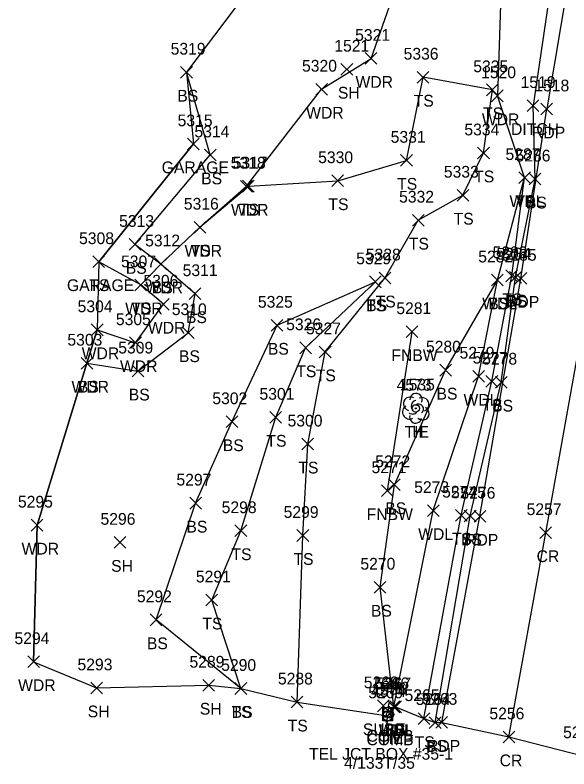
# Model space of a CAD drawing. Extents: x 1509053 to 1511576, y 400838 to 402572.
# Drawn here: x 1509634.8 to 1509729.1, y 401157.7 to 401286.1 of the extents above; entities that cross this region are included whole.
import ezdxf

# ---------------------------------------------------------------- set-up
doc = ezdxf.new("R2010")
doc.units = 0
for name, color, linetype in [('C_A', 7, 'Continuous'), ('C_I', 7, 'Continuous'), ('CBP', 7, 'Continuous'), ('D_A', 7, 'Continuous'), ('D_I', 7, 'Continuous'), ('D_TIC', 7, 'Continuous'), ('DD', 7, 'Continuous'), ('L_A', 7, 'Continuous'), ('L_I', 7, 'Continuous'), ('L_TIC', 7, 'Continuous'), ('LAWA', 7, 'Continuous'), ('LBC', 7, 'Continuous'), ('LELB', 7, 'Continuous'), ('LFNC', 7, 'Continuous'), ('LSOGP', 7, 'Continuous'), ('LTD', 7, 'Continuous'), ('P_A', 7, 'Continuous'), ('P_I', 7, 'Continuous'), ('P_TIC', 7, 'Continuous'), ('PET', 7, 'Continuous'), ('PRC', 7, 'Continuous'), ('U_A', 7, 'Continuous'), ('U_C', 7, 'Continuous'), ('U_I', 7, 'Continuous'), ('U_TIC', 7, 'Continuous'), ('UDEFAULT', 7, 'Continuous'), ('UP', 7, 'Continuous')]:
    doc.layers.add(name, color=color, linetype=linetype)

msp = doc.modelspace()

# ---------------------------------------------------------------- linework, layer by layer
at = {"layer": 'CBP'}
for centre, radius in [((1509703.04, 401219.14), 0.625), ((1509703.04, 401219.14), 0.0833), ((1509698.7, 401167), 0.625), ((1509698.7, 401167), 0.0833)]:
    msp.add_circle(centre, radius, dxfattribs=at)
at = {"layer": 'D_TIC'}
for points in [[(1509722.02, 401269.7), (1509724.02, 401271.7)], [(1509724.02, 401269.7), (1509722.02, 401271.7)]]:
    msp.add_lwpolyline(points, dxfattribs=at)
at = {"layer": 'DD'}
msp.add_lwpolyline([(1509730.43, 401320.85), (1509723.02, 401270.7)], dxfattribs=at)
at = {"layer": 'L_TIC'}
for points in [[(1509694.42, 401277.73), (1509696.42, 401279.73)], [(1509696.42, 401277.73), (1509694.42, 401279.73)], [(1509663, 401275.38), (1509665, 401277.38)], [(1509665, 401275.38), (1509663, 401277.38)], [(1509690.3, 401275.88), (1509692.3, 401277.88)], [(1509692.3, 401275.88), (1509690.3, 401277.88)], [(1509703.28, 401274.53), (1509705.28, 401276.53)], [(1509705.28, 401274.53), (1509703.28, 401276.53)], [(1509703.28, 401274.53), (1509705.28, 401276.53)], [(1509705.28, 401274.53), (1509703.28, 401276.53)], [(1509686.01, 401272.48), (1509688.01, 401274.48)], [(1509688.01, 401272.48), (1509686.01, 401274.48)], [(1509715.09, 401272.38), (1509717.09, 401274.38)], [(1509717.09, 401272.38), (1509715.09, 401274.38)], [(1509715.94, 401271.36), (1509717.94, 401273.36)], [(1509717.94, 401271.36), (1509715.94, 401273.36)], [(1509664.18, 401263.18), (1509666.18, 401265.18)], [(1509666.18, 401263.18), (1509664.18, 401265.18)], [(1509667.06, 401261.29), (1509669.06, 401263.29)], [(1509669.06, 401261.29), (1509667.06, 401263.29)], [(1509713.58, 401261.63), (1509715.58, 401263.63)], [(1509715.58, 401261.63), (1509713.58, 401263.63)], [(1509700.47, 401260.37), (1509702.47, 401262.37)], [(1509702.47, 401260.37), (1509700.47, 401262.37)], [(1509720.58, 401257.43), (1509722.58, 401259.43)], [(1509722.58, 401257.43), (1509720.58, 401259.43)], [(1509720.58, 401257.43), (1509722.58, 401259.43)], [(1509722.58, 401257.43), (1509720.58, 401259.43)], [(1509722.35, 401257.18), (1509724.35, 401259.18)], [(1509724.35, 401257.18), (1509722.35, 401259.18)], [(1509673.22, 401255.95), (1509675.22, 401257.95)], [(1509675.22, 401255.95), (1509673.22, 401257.95)], [(1509673.55, 401255.98), (1509675.55, 401257.98)], [(1509675.55, 401255.98), (1509673.55, 401257.98)], [(1509688.76, 401256.9), (1509690.76, 401258.9)], [(1509690.76, 401256.9), (1509688.76, 401258.9)], [(1509710.08, 401254.43), (1509712.08, 401256.43)], [(1509712.08, 401254.43), (1509710.08, 401256.43)], [(1509702.46, 401250.18), (1509704.46, 401252.18)], [(1509704.46, 401250.18), (1509702.46, 401252.18)], [(1509665.3, 401248.98), (1509667.3, 401250.98)], [(1509667.3, 401248.98), (1509665.3, 401250.98)], [(1509665.3, 401248.98), (1509667.3, 401250.98)], [(1509667.3, 401248.98), (1509665.3, 401250.98)], [(1509654.23, 401246.05), (1509656.23, 401248.05)], [(1509656.23, 401246.05), (1509654.23, 401248.05)], [(1509648.05, 401243.11), (1509650.05, 401245.11)], [(1509650.05, 401243.11), (1509648.05, 401245.11)], [(1509648.05, 401243.11), (1509650.05, 401245.11)], [(1509650.05, 401243.11), (1509648.05, 401245.11)], [(1509658.66, 401242.72), (1509660.66, 401244.72)], [(1509660.66, 401242.72), (1509658.66, 401244.72)], [(1509658.66, 401242.72), (1509660.66, 401244.72)], [(1509660.66, 401242.72), (1509658.66, 401244.72)], [(1509696.8, 401240.33), (1509698.8, 401242.33)], [(1509698.8, 401240.33), (1509696.8, 401242.33)], [(1509718.38, 401240.71), (1509720.38, 401242.71)], [(1509720.38, 401240.71), (1509718.38, 401242.71)], [(1509719.02, 401240.47), (1509721.02, 401242.47)], [(1509721.02, 401240.47), (1509719.02, 401242.47)], [(1509655.2, 401239.16), (1509657.2, 401241.16)], [(1509657.2, 401239.16), (1509655.2, 401241.16)], [(1509655.2, 401239.16), (1509657.2, 401241.16)], [(1509657.2, 401239.16), (1509655.2, 401241.16)], [(1509695.16, 401239.68), (1509697.16, 401241.68)], [(1509697.16, 401239.68), (1509695.16, 401241.68)], [(1509695.16, 401239.68), (1509697.16, 401241.68)], [(1509697.16, 401239.68), (1509695.16, 401241.68)], [(1509715.94, 401239.99), (1509717.94, 401241.99)], [(1509717.94, 401239.99), (1509715.94, 401241.99)], [(1509715.94, 401239.99), (1509717.94, 401241.99)], [(1509717.94, 401239.99), (1509715.94, 401241.99)], [(1509664.47, 401237.66), (1509666.47, 401239.66)], [(1509666.47, 401237.66), (1509664.47, 401239.66)], [(1509659.07, 401235.87), (1509661.07, 401237.87)], [(1509661.07, 401235.87), (1509659.07, 401237.87)], [(1509647.79, 401231.51), (1509649.79, 401233.51)], [(1509649.79, 401231.51), (1509647.79, 401233.51)], [(1509678.42, 401232.28), (1509680.42, 401234.28)], [(1509680.42, 401232.28), (1509678.42, 401234.28)], [(1509663.28, 401231.02), (1509665.28, 401233.02)], [(1509665.28, 401231.02), (1509663.28, 401233.02)], [(1509701.42, 401231.19), (1509703.42, 401233.19)], [(1509703.42, 401231.19), (1509701.42, 401233.19)], [(1509654.32, 401229.31), (1509656.32, 401231.31)], [(1509656.32, 401229.31), (1509654.32, 401231.31)], [(1509683.29, 401228.45), (1509685.29, 401230.45)], [(1509685.29, 401228.45), (1509683.29, 401230.45)], [(1509686.61, 401227.75), (1509688.61, 401229.75)], [(1509688.61, 401227.75), (1509686.61, 401229.75)], [(1509646.06, 401225.82), (1509648.06, 401227.82)], [(1509648.06, 401225.82), (1509646.06, 401227.82)], [(1509646.06, 401225.82), (1509648.06, 401227.82)], [(1509648.06, 401225.82), (1509646.06, 401227.82)], [(1509654.73, 401224.48), (1509656.73, 401226.48)], [(1509656.73, 401224.48), (1509654.73, 401226.48)], [(1509707.13, 401224.64), (1509709.13, 401226.64)], [(1509709.13, 401224.64), (1509707.13, 401226.64)], [(1509712.75, 401223.61), (1509714.75, 401225.61)], [(1509714.75, 401223.61), (1509712.75, 401225.61)], [(1509714.99, 401222.76), (1509716.99, 401224.76)], [(1509716.99, 401222.76), (1509714.99, 401224.76)], [(1509716.61, 401222.59), (1509718.61, 401224.59)], [(1509718.61, 401222.59), (1509716.61, 401224.59)], [(1509678.2, 401216.61), (1509680.2, 401218.61)], [(1509680.2, 401216.61), (1509678.2, 401218.61)], [(1509670.74, 401215.85), (1509672.74, 401217.85)], [(1509672.74, 401215.85), (1509670.74, 401217.85)], [(1509683.64, 401212.05), (1509685.64, 401214.05)], [(1509685.64, 401212.05), (1509683.64, 401214.05)], [(1509698.4, 401205.12), (1509700.4, 401207.12)], [(1509700.4, 401205.12), (1509698.4, 401207.12)], [(1509697.21, 401204.1), (1509699.21, 401206.1)], [(1509699.21, 401204.1), (1509697.21, 401206.1)], [(1509664.55, 401201.99), (1509666.55, 401203.99)], [(1509666.55, 401201.99), (1509664.55, 401203.99)], [(1509705.03, 401200.72), (1509707.03, 401202.72)], [(1509707.03, 401200.72), (1509705.03, 401202.72)], [(1509709.79, 401199.94), (1509711.79, 401201.94)], [(1509711.79, 401199.94), (1509709.79, 401201.94)], [(1509711.3, 401199.82), (1509713.3, 401201.82)], [(1509713.3, 401199.82), (1509711.3, 401201.82)], [(1509637.56, 401198.24), (1509639.56, 401200.24)], [(1509639.56, 401198.24), (1509637.56, 401200.24)], [(1509672.25, 401197.29), (1509674.25, 401199.29)], [(1509674.25, 401197.29), (1509672.25, 401199.29)], [(1509682.81, 401196.48), (1509684.81, 401198.48)], [(1509684.81, 401196.48), (1509682.81, 401198.48)], [(1509651.68, 401195.31), (1509653.68, 401197.31)], [(1509653.68, 401195.31), (1509651.68, 401197.31)], [(1509695.96, 401187.67), (1509697.96, 401189.67)], [(1509697.96, 401187.67), (1509695.96, 401189.67)], [(1509667.29, 401185.49), (1509669.29, 401187.49)], [(1509669.29, 401185.49), (1509667.29, 401187.49)], [(1509657.82, 401182.12), (1509659.82, 401184.12)], [(1509659.82, 401182.12), (1509657.82, 401184.12)], [(1509636.97, 401174.99), (1509638.97, 401176.99)], [(1509638.97, 401174.99), (1509636.97, 401176.99)], [(1509666.78, 401170.98), (1509668.78, 401172.98)], [(1509668.78, 401170.98), (1509666.78, 401172.98)], [(1509647.7, 401170.52), (1509649.7, 401172.52)], [(1509649.7, 401170.52), (1509647.7, 401172.52)], [(1509672.26, 401170.43), (1509674.26, 401172.43)], [(1509674.26, 401170.43), (1509672.26, 401172.43)], [(1509672.26, 401170.43), (1509674.26, 401172.43)], [(1509674.26, 401170.43), (1509672.26, 401172.43)], [(1509681.83, 401168.11), (1509683.83, 401170.11)], [(1509683.83, 401168.11), (1509681.83, 401170.11)], [(1509698.31, 401167.31), (1509700.31, 401169.31)], [(1509700.31, 401167.31), (1509698.31, 401169.31)], [(1509698.31, 401167.31), (1509700.31, 401169.31)], [(1509700.31, 401167.31), (1509698.31, 401169.31)], [(1509703.44, 401165.29), (1509705.44, 401167.29)], [(1509705.44, 401165.29), (1509703.44, 401167.29)], [(1509705.35, 401164.63), (1509707.35, 401166.63)], [(1509707.35, 401164.63), (1509705.35, 401166.63)]]:
    msp.add_lwpolyline(points, dxfattribs=at)
at = {"layer": 'LAWA'}
for points in [[(1509718.6, 401322.35), (1509716.94, 401272.36)], [(1509637.97, 401175.99), (1509638.56, 401199.24), (1509647.06, 401226.82), (1509648.79, 401232.51), (1509655.32, 401230.31), (1509660.07, 401236.87), (1509656.2, 401240.16), (1509659.66, 401243.72), (1509666.3, 401249.98), (1509674.22, 401256.95), (1509687.01, 401273.48), (1509695.42, 401278.73), (1509701.27, 401295.44), (1509681.69, 401309.59)], [(1509721.58, 401258.43), (1509716.94, 401272.36)], [(1509699.31, 401168.31), (1509706.03, 401201.72), (1509713.75, 401224.61), (1509716.94, 401240.99), (1509721.58, 401258.43)]]:
    msp.add_lwpolyline(points, dxfattribs=at)
at = {"layer": 'LBC'}
msp.add_lwpolyline([(1509649.05, 401244.11), (1509665.18, 401264.18)], dxfattribs=at)
at = {"layer": 'LELB'}
for points in [[(1509647.06, 401226.82), (1509655.73, 401225.48), (1509664.28, 401232.02), (1509665.47, 401238.66), (1509659.66, 401243.72), (1509655.23, 401247.05), (1509668.06, 401262.29), (1509664, 401276.38)], [(1509666.3, 401249.98), (1509674.55, 401256.98), (1509689.76, 401257.9), (1509701.47, 401261.37), (1509704.28, 401275.53)], [(1509682.83, 401169.11), (1509683.81, 401197.48), (1509684.64, 401213.05), (1509687.61, 401228.75), (1509697.8, 401241.33), (1509703.46, 401251.18), (1509711.08, 401255.43), (1509714.58, 401262.63), (1509716.09, 401273.38), (1509704.28, 401275.53)], [(1509723.35, 401258.18), (1509723.02, 401270.7)], [(1509704.44, 401166.29), (1509710.79, 401200.94), (1509715.99, 401223.76), (1509719.38, 401241.71), (1509721.58, 401258.43)], [(1509706.35, 401165.63), (1509712.3, 401200.82), (1509717.61, 401223.59), (1509720.02, 401241.47), (1509723.35, 401258.18)], [(1509656.2, 401240.16), (1509649.05, 401244.11)], [(1509673.26, 401171.43), (1509658.82, 401183.12), (1509665.55, 401202.99), (1509671.74, 401216.85), (1509679.42, 401233.28), (1509696.16, 401240.68)], [(1509673.26, 401171.43), (1509668.29, 401186.49), (1509673.25, 401198.29), (1509679.2, 401217.61), (1509684.29, 401229.45), (1509696.16, 401240.68)], [(1509699.31, 401168.31), (1509696.96, 401188.67), (1509699.4, 401206.12), (1509708.13, 401225.64), (1509716.94, 401240.99)]]:
    msp.add_lwpolyline(points, dxfattribs=at)
at = {"layer": 'LFNC'}
msp.add_lwpolyline([(1509698.21, 401205.1), (1509702.42, 401232.19)], dxfattribs=at)
at = {"layer": 'LSOGP'}
msp.add_lwpolyline([(1509676.9, 401293.5), (1509664, 401276.38), (1509665.18, 401264.18), (1509649.05, 401244.11), (1509648.79, 401232.51), (1509647.06, 401226.82), (1509638.56, 401199.24), (1509637.97, 401175.99), (1509648.7, 401171.52), (1509667.78, 401171.98), (1509673.26, 401171.43), (1509682.83, 401169.11), (1509698.26, 401166.76), (1509699.6, 401168.3), (1509704.44, 401166.29), (1509706.35, 401165.63), (1509707.47, 401165.66), (1509718.9, 401163.18), (1509731.47, 401159.97)], dxfattribs=at)
at = {"layer": 'LTD'}
msp.add_line((1509703.03, 401219.2), (1509703.03, 401219.2), dxfattribs=at)
msp.add_line((1509703.03, 401219.2), (1509703.03, 401219.2), dxfattribs=at)
msp.add_arc((1509703.08, 401220.63), 1.05, 335.5272, 180.9563, dxfattribs=at)
for centre, major_axis, ratio, start_param, end_param in [((1509702.24, 401219.87), (1.21, -0.51), 0.895232, 1.570796, 4.712389), ((1509702.82, 401219.66), (-0.208, -0.792), 0.645439, 3.141593, 6.283185), ((1509704.07, 401219.78), (-1.14, -0.48), 0.949671, 1.570796, 4.712389), ((1509701.95, 401218.49), (0.58, -1.04), 0.959034, 3.141593, 6.283185), ((1509703.53, 401219.03), (-0.5, 0.667), 0.989748, 3.141593, 6.283185), ((1509704.03, 401218.37), (-1.09, 0.79), 0.841452, 1.570796, 4.712389), ((1509703.03, 401217.7), (0.26, 1.06), 0.942809, 1.570796, 4.712389), ((1509702.57, 401218.45), (-0.625, -0.083), 0.423636, 0, 3.141593)]:
    msp.add_ellipse(centre, major_axis=major_axis, ratio=ratio, start_param=start_param, end_param=end_param, dxfattribs=at)
at = {"layer": 'P_TIC'}
for points in [[(1509724.35, 401269.12), (1509726.35, 401271.12)], [(1509726.35, 401269.12), (1509724.35, 401271.12)], [(1509719.93, 401240.28), (1509721.93, 401242.28)], [(1509721.93, 401240.28), (1509719.93, 401242.28)], [(1509712.96, 401199.75), (1509714.96, 401201.75)], [(1509714.96, 401199.75), (1509712.96, 401201.75)], [(1509724.18, 401196.96), (1509726.18, 401198.96)], [(1509726.18, 401196.96), (1509724.18, 401198.96)], [(1509706.47, 401164.66), (1509708.47, 401166.66)], [(1509708.47, 401164.66), (1509706.47, 401166.66)], [(1509717.9, 401162.18), (1509719.9, 401164.18)], [(1509719.9, 401162.18), (1509717.9, 401164.18)]]:
    msp.add_lwpolyline(points, dxfattribs=at)
at = {"layer": 'PET'}
for points in [[(1509741.68, 401369.7), (1509733.72, 401319.89), (1509725.35, 401270.12)], [(1509720.93, 401241.28), (1509725.35, 401270.12)], [(1509707.47, 401165.66), (1509713.96, 401200.75), (1509720.93, 401241.28)]]:
    msp.add_lwpolyline(points, dxfattribs=at)
at = {"layer": 'PRC'}
msp.add_lwpolyline([(1509718.9, 401163.18), (1509725.18, 401197.96), (1509732.62, 401239.49)], dxfattribs=at)
at = {"layer": 'U_TIC'}
for points in [[(1509696.5, 401167.47), (1509698.5, 401169.47)], [(1509698.5, 401167.47), (1509696.5, 401169.47)]]:
    msp.add_lwpolyline(points, dxfattribs=at)
at = {"layer": 'UDEFAULT'}
for points in [[(1509698.6, 401167.3), (1509700.6, 401169.3)], [(1509700.6, 401167.3), (1509698.6, 401169.3)]]:
    msp.add_lwpolyline(points, dxfattribs=at)
at = {"layer": 'UP'}
for p, q in [((1509697.44, 401166.53), (1509697.44, 401168.2)), ((1509697.44, 401168.2), (1509699.11, 401168.2)), ((1509698.51, 401168.43), (1509698.26, 401167.59)), ((1509698.52, 401169.03), (1509698.27, 401168.2)), ((1509699.11, 401168.2), (1509699.11, 401166.53)), ((1509697.43, 401165.93), (1509697.43, 401167.59)), ((1509697.43, 401167.59), (1509699.09, 401167.59)), ((1509698.26, 401166.76), (1509698.26, 401166.76)), ((1509698.27, 401167.37), (1509698.27, 401167.37)), ((1509699.09, 401167.59), (1509699.09, 401165.93)), ((1509699.09, 401165.93), (1509697.43, 401165.93)), ((1509699.11, 401166.53), (1509697.44, 401166.53)), ((1509698.01, 401165.09), (1509698.26, 401165.93)), ((1509698.02, 401165.7), (1509698.27, 401166.53))]:
    msp.add_line(p, q, dxfattribs=at)
for centre in [(1509698.27, 401167.37), (1509698.26, 401166.76)]:
    msp.add_circle(centre, 0.833, dxfattribs=at)

# ---------------------------------------------------------------- texts
at = {"layer": 'C_A'}
for p in [(1509701.12, 401214.14), (1509696.78, 401162)]:
    msp.add_text('TIE', height=2, dxfattribs=at).set_placement(p)
at = {"layer": 'C_I'}
for s, p in [('4573', (1509699.78, 401222.14)), ('4574', (1509695.44, 401170))]:
    msp.add_text(s, height=2, dxfattribs=at).set_placement(p)
at = {"layer": 'D_A'}
msp.add_text('DITCH', height=2, dxfattribs=at).set_placement((1509719.26, 401265.7))
at = {"layer": 'D_I'}
msp.add_text('1519', height=2, dxfattribs=at).set_placement((1509720.89, 401273.7))
at = {"layer": 'L_A'}
for s, p in [('WDR', (1509692.78, 401273.73)), ('BS', (1509662.44, 401271.38)), ('SH', (1509689.78, 401271.89)), ('TS', (1509702.69, 401270.53)), ('TS', (1509702.69, 401270.53)), ('WDR', (1509684.38, 401268.48)), ('WDR', (1509714.3, 401267.36)), ('TS', (1509714.5, 401268.38)), ('GARAGE', (1509659.78, 401259.18)), ('BS', (1509666.5, 401257.29)), ('TS', (1509712.99, 401257.63)), ('TS', (1509699.87, 401256.37)), ('WDL', (1509719, 401253.43)), ('TS', (1509719.99, 401253.43)), ('BS', (1509721.79, 401253.18)), ('WDR', (1509671.58, 401251.95)), ('TS', (1509672.96, 401251.98)), ('TS', (1509688.17, 401252.9)), ('TS', (1509709.49, 401250.43)), ('TS', (1509701.87, 401246.18)), ('WDR', (1509663.67, 401244.98)), ('TS', (1509664.71, 401244.98)), ('BS', (1509653.67, 401242.05)), ('GARAGE', (1509643.65, 401239.11)), ('TS', (1509647.46, 401239.11)), ('WDR', (1509657.02, 401238.72)), ('BS', (1509658.1, 401238.72)), ('TS', (1509717.79, 401236.71)), ('BS', (1509718.46, 401236.47)), ('WDR', (1509653.56, 401235.16)), ('TS', (1509654.61, 401235.16)), ('TS', (1509694.57, 401235.68)), ('BS', (1509694.6, 401235.68)), ('TS', (1509696.21, 401236.33)), ('WDL', (1509714.36, 401235.99)), ('BS', (1509715.38, 401235.99)), ('BS', (1509663.91, 401233.66)), ('WDR', (1509657.43, 401231.87)), ('WDR', (1509646.16, 401227.51)), ('BS', (1509677.86, 401228.28)), ('BS', (1509662.72, 401227.02)), ('FNBW', (1509698.89, 401227.19)), ('WDR', (1509652.68, 401225.31)), ('TS', (1509682.7, 401224.45)), ('TS', (1509686.02, 401223.75)), ('WDR', (1509644.42, 401221.82)), ('BS', (1509645.5, 401221.82)), ('BS', (1509654.17, 401220.48)), ('BS', (1509706.57, 401220.64)), ('WDL', (1509711.17, 401219.61)), ('TS', (1509714.4, 401218.76)), ('BS', (1509716.05, 401218.59)), ('H', (1509702.46, 401214.2)), ('TS', (1509677.61, 401212.61)), ('BS', (1509670.18, 401211.85)), ('TS', (1509683.05, 401208.05)), ('BS', (1509697.84, 401201.12)), ('FNBW', (1509694.68, 401200.1)), ('BS', (1509663.99, 401197.99)), ('WDL', (1509703.45, 401196.72)), ('TS', (1509709.2, 401195.94)), ('BS', (1509710.74, 401195.82)), ('WDR', (1509635.92, 401194.24)), ('TS', (1509671.66, 401193.29)), ('TS', (1509682.22, 401192.48)), ('SH', (1509651.17, 401191.31)), ('BS', (1509695.4, 401183.67)), ('TS', (1509666.7, 401181.49)), ('BS', (1509657.26, 401178.12)), ('WDR', (1509635.33, 401170.99)), ('SH', (1509647.19, 401166.52)), ('SH', (1509666.27, 401166.98)), ('TS', (1509671.67, 401166.43)), ('BS', (1509671.7, 401166.43)), ('TS', (1509681.24, 401164.11)), ('WDL', (1509696.73, 401163.31)), ('BS', (1509697.75, 401163.31)), ('TS', (1509702.85, 401161.29)), ('BS', (1509704.79, 401160.63))]:
    msp.add_text(s, height=2, dxfattribs=at).set_placement(p)
at = {"layer": 'L_I'}
for s, p in [('5321', (1509692.72, 401281.73)), ('5319', (1509661.3, 401279.38)), ('1521', (1509689.17, 401279.89)), ('5336', (1509700.97, 401278.53)), ('5336', (1509700.97, 401278.53)), ('5320', (1509683.67, 401276.48)), ('5335', (1509712.83, 401276.38)), ('1520', (1509714.16, 401275.36)), ('5315', (1509662.49, 401267.18)), ('5314', (1509665.36, 401265.29)), ('5334', (1509711.32, 401265.63)), ('5331', (1509698.77, 401264.37)), ('5330', (1509686.42, 401260.9)), ('5287', (1509718.32, 401261.43)), ('5287', (1509718.32, 401261.43)), ('5286', (1509720.03, 401261.18)), ('5318', (1509671.53, 401259.95)), ('5317', (1509671.86, 401259.98)), ('5333', (1509707.82, 401258.43)), ('5332', (1509700.2, 401254.18)), ('5316', (1509663.55, 401252.98)), ('5316', (1509663.55, 401252.98)), ('5313', (1509652.53, 401250.05)), ('5308', (1509645.71, 401247.11)), ('5308', (1509645.71, 401247.11)), ('5312', (1509656.96, 401246.72)), ('5312', (1509656.96, 401246.72)), ('5328', (1509694.54, 401244.33)), ('5283', (1509716.12, 401244.71)), ('5284', (1509716.76, 401244.47)), ('5307', (1509652.86, 401243.16)), ('5307', (1509652.86, 401243.16)), ('5329', (1509692.89, 401243.68)), ('5329', (1509692.89, 401243.68)), ('5282', (1509713.68, 401243.99)), ('5282', (1509713.68, 401243.99)), ('5311', (1509663.35, 401241.66)), ('5306', (1509656.67, 401239.87)), ('5304', (1509645.46, 401235.51)), ('5325', (1509676.16, 401236.28)), ('5281', (1509699.73, 401235.19)), ('5310', (1509661.5, 401235.02)), ('5305', (1509651.98, 401233.31)), ('5326', (1509680.97, 401232.45)), ('5327', (1509684.35, 401231.75)), ('5303', (1509643.72, 401229.82)), ('5303', (1509643.72, 401229.82)), ('5309', (1509652.38, 401228.48)), ('5280', (1509704.78, 401228.64)), ('5279', (1509710.49, 401227.61)), ('5277', (1509712.73, 401226.76)), ('5278', (1509714.35, 401226.59)), ('1535', (1509700.34, 401222.2)), ('5302', (1509668.4, 401219.85)), ('5301', (1509676.43, 401220.61)), ('5300', (1509681.21, 401216.05)), ('5272', (1509696.14, 401209.12)), ('5271', (1509695.51, 401208.1)), ('5297', (1509662.29, 401205.99)), ('5273', (1509702.77, 401204.72)), ('5274', (1509707.53, 401203.94)), ('5275', (1509709.04, 401203.82)), ('5295', (1509635.3, 401202.24)), ('5298', (1509669.99, 401201.29)), ('5299', (1509680.54, 401200.48)), ('5296', (1509649.36, 401199.31)), ('5270', (1509693.61, 401191.67)), ('5291', (1509665.6, 401189.49)), ('5292', (1509655.56, 401186.12)), ('5294', (1509634.71, 401178.99)), ('5289', (1509664.51, 401174.98)), ('5293', (1509645.44, 401174.52)), ('5290', (1509669.91, 401174.43)), ('5290', (1509669.91, 401174.43)), ('5288', (1509679.57, 401172.11)), ('5266', (1509695.95, 401171.31)), ('5266', (1509695.95, 401171.31)), ('5265', (1509701.13, 401169.29)), ('5264', (1509703.04, 401168.63))]:
    msp.add_text(s, height=2, dxfattribs=at).set_placement(p)
at = {"layer": 'P_A'}
for s, p in [('RDP', (1509722.84, 401265.12)), ('RDP', (1509718.42, 401236.28)), ('RDP', (1509711.45, 401195.75)), ('CR', (1509723.62, 401192.96)), ('RDP', (1509704.96, 401160.66)), ('CR', (1509717.33, 401158.18))]:
    msp.add_text(s, height=2, dxfattribs=at).set_placement(p)
at = {"layer": 'P_I'}
for s, p in [('1518', (1509723.23, 401273.12)), ('5285', (1509717.67, 401244.28)), ('5276', (1509710.65, 401203.75)), ('5257', (1509721.92, 401200.96)), ('5263', (1509704.17, 401168.66)), ('5256', (1509715.58, 401166.18)), ('5220', (1509728.13, 401162.97))]:
    msp.add_text(s, height=2, dxfattribs=at).set_placement(p)
at = {"layer": 'U_A'}
for s, p in [('SUBE', (1509694.03, 401163.47)), ('UTIL', (1509696.76, 401163.3)), ('COMB', (1509694.66, 401162.37)), ('COMB', (1509694.65, 401161.76))]:
    msp.add_text(s, height=2, dxfattribs=at).set_placement(p)
at = {"layer": 'U_C'}
for s, p in [('TEL JCT BOX #35-1', (1509684.86, 401159.3)), ('4/133T/35', (1509690.84, 401157.76))]:
    msp.add_text(s, height=2, dxfattribs=at).set_placement(p)
at = {"layer": 'U_I'}
for s, p in [('5268', (1509694.19, 401171.47)), ('5267', (1509696.29, 401171.3)), ('5269', (1509694.95, 401169.76)), ('1536', (1509695.52, 401170.37))]:
    msp.add_text(s, height=2, dxfattribs=at).set_placement(p)

doc.saveas('drawing.dxf')
